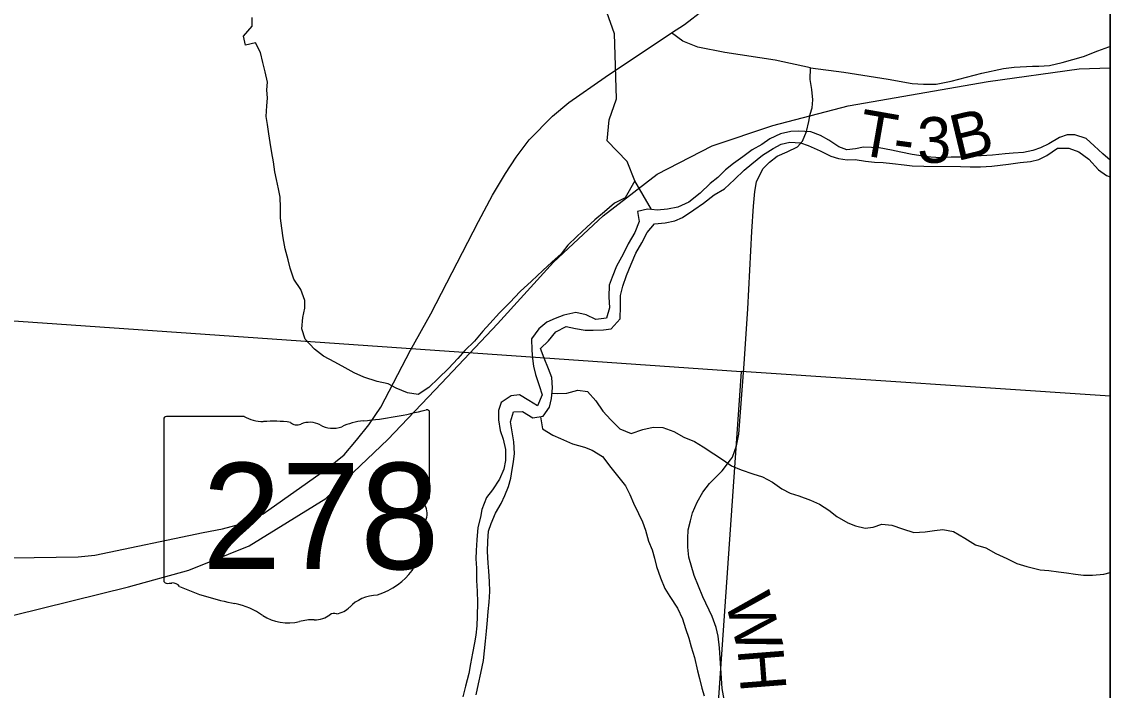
# Model space of a CAD drawing. Extents: x 0 to 34, y 0 to 22.
# Drawn here: x 7.55 to 8.9, y 19.403 to 20.232 of the extents above; entities that cross this region are included whole.
import ezdxf

# ---------------------------------------------------------------- set-up
doc = ezdxf.new("R2010")
doc.units = 0
for name, color, linetype in [('Default', 7, 'Continuous'), ('GM_X_County_Road', 7, 'Continuous'), ('GM_X_County_Road_Text', 7, 'Continuous'), ('GM_X_Major_River', 7, 'Continuous'), ('GM_X_Minor_River', 7, 'Continuous'), ('GM_X_Rail_Line', 7, 'Continuous'), ('GM_X_Section', 7, 'Continuous'), ('GM_X_State_Location', 7, 'Continuous'), ('GM_X_State_Route', 7, 'Continuous'), ('GM_X_State_Shield', 7, 'Continuous'), ('GM_X_Township_Road', 7, 'Continuous'), ('GM_X_Township_Road_Text', 7, 'Continuous'), ('SC_Scratch1', 7, 'Continuous'), ('SH_Data', 7, 'Continuous')]:
    doc.layers.add(name, color=color, linetype=linetype)

msp = doc.modelspace()

# ---------------------------------------------------------------- linework, layer by layer
at = {"layer": 'Default'}
msp.add_lwpolyline([(8.9, 18.739), (8.9, 19.7676), (8.4423, 19.798), (8.3709, 18.7757)], close=True, dxfattribs=at)
at = {"layer": 'GM_X_County_Road'}
msp.add_lwpolyline([(8.421, 19.3911), (8.4184, 19.4049), (8.4154, 19.4552), (8.4137, 19.47), (8.4111, 19.4808), (8.406, 19.4942), (8.3947, 19.5188), (8.3839, 19.5452), (8.3774, 19.5679), (8.3759, 19.5801), (8.3759, 19.5912), (8.3766, 19.6018), (8.3794, 19.613), (8.3818, 19.6227), (8.3875, 19.6359), (8.3945, 19.6485), (8.4029, 19.6591), (8.4184, 19.675), (8.4288, 19.6884), (8.4314, 19.6921), (8.4363, 19.706), (8.4391, 19.7203), (8.4459, 19.8075), (8.4504, 19.8758), (8.4556, 19.9719), (8.4574, 20.0031), (8.459, 20.0216), (8.4614, 20.0336), (8.4691, 20.0496), (8.4774, 20.0578), (8.4868, 20.0653), (8.4994, 20.0707), (8.5119, 20.0768), (8.5183, 20.0841), (8.5231, 20.0958), (8.526, 20.1081), (8.5279, 20.1175), (8.5302, 20.1254), (8.5311, 20.1351), (8.5298, 20.148), (8.5278, 20.1602), (8.5281, 20.1748), (8.4844, 20.1843), (8.422, 20.1941), (8.3884, 20.2005), (8.37, 20.2081), (8.3557, 20.2182)], dxfattribs=at)
at = {"layer": 'GM_X_Major_River'}
for points in [[(8.3104, 20.0348), (8.3009, 20.0587), (8.2758, 20.0845), (8.2784, 20.1103), (8.2874, 20.1365), (8.2866, 20.1631), (8.2858, 20.1908), (8.2849, 20.217), (8.2754, 20.244), (8.267, 20.2694), (8.2746, 20.283)], [(8.7924, 20.07), (8.7795, 20.0689), (8.7697, 20.0681), (8.7541, 20.0666), (8.7397, 20.0659), (8.7257, 20.0648), (8.7158, 20.064), (8.7025, 20.064), (8.69, 20.0633), (8.6775, 20.0641), (8.668, 20.0652), (8.6543, 20.0675), (8.6403, 20.0702), (8.6285, 20.0728), (8.6134, 20.0755), (8.6039, 20.0759), (8.594, 20.0763), (8.5838, 20.0744), (8.5731, 20.0733), (8.5633, 20.0767), (8.5508, 20.0851), (8.5405, 20.0911), (8.5284, 20.0953), (8.5136, 20.0965), (8.5037, 20.0961), (8.4908, 20.0931), (8.4779, 20.0866), (8.4677, 20.0798), (8.4559, 20.073), (8.4441, 20.0643), (8.4327, 20.0563), (8.4229, 20.0484), (8.4134, 20.0389), (8.4039, 20.0313), (8.3914, 20.0192), (8.3773, 20.0082), (8.3636, 20.0021), (8.3507, 19.9995), (8.3378, 19.9983), (8.331, 19.999)], [(8.9, 20.0604), (8.8907, 20.068), (8.8801, 20.0783), (8.8702, 20.0874), (8.8562, 20.0916), (8.8467, 20.0916), (8.8372, 20.0886), (8.8239, 20.0806), (8.8137, 20.0757), (8.8038, 20.0723), (8.7924, 20.07)], [(8.1194, 19.4238), (8.1224, 19.4398), (8.1239, 19.4515), (8.1251, 19.4637), (8.1262, 19.4762), (8.1274, 19.4895), (8.1285, 19.5005), (8.1297, 19.5119), (8.1304, 19.5252), (8.13, 19.5377), (8.1293, 19.5506), (8.1285, 19.5605), (8.1274, 19.5749), (8.1278, 19.5878), (8.1289, 19.6), (8.132, 19.6098), (8.1373, 19.6223), (8.1445, 19.6345), (8.1491, 19.6444), (8.1536, 19.6557), (8.1563, 19.666), (8.1582, 19.6766), (8.1597, 19.6861), (8.1609, 19.6963), (8.1601, 19.7108), (8.156, 19.7358), (8.1598, 19.7483), (8.1708, 19.7487), (8.1837, 19.7407), (8.1966, 19.7426), (8.2045, 19.754), (8.2068, 19.7646), (8.2083, 19.7779), (8.2072, 19.7908), (8.203, 19.8015), (8.1977, 19.8147), (8.1932, 19.8269), (8.2031, 19.8364), (8.2122, 19.8474), (8.2251, 19.8538), (8.2365, 19.8515), (8.2486, 19.8496), (8.2585, 19.8496), (8.2714, 19.85), (8.2809, 19.8511), (8.2919, 19.8636), (8.2926, 19.8792), (8.2923, 19.8925), (8.2953, 19.9042), (8.2999, 19.9171), (8.3056, 19.9315), (8.3116, 19.9448), (8.3189, 19.9577), (8.3257, 19.9706), (8.3348, 19.9813), (8.3477, 19.9824), (8.3598, 19.985), (8.3693, 19.9892), (8.3834, 19.9987), (8.3955, 20.007), (8.4088, 20.0172), (8.4213, 20.0248), (8.4339, 20.0362), (8.446, 20.048), (8.4555, 20.0559), (8.4688, 20.0665), (8.4817, 20.0749), (8.4916, 20.0802), (8.5026, 20.0828), (8.5158, 20.082), (8.5253, 20.0786), (8.5401, 20.0718), (8.5534, 20.0653), (8.5629, 20.0623), (8.5735, 20.0607), (8.5834, 20.0611), (8.5966, 20.0592), (8.6076, 20.058), (8.6183, 20.0573), (8.6297, 20.0561), (8.6445, 20.0546), (8.6543, 20.0534), (8.6687, 20.0527), (8.7143, 20.0526), (8.7264, 20.0522), (8.7389, 20.0522), (8.753, 20.053), (8.7636, 20.0541), (8.7738, 20.0552), (8.7883, 20.0575), (8.8012, 20.0586), (8.8114, 20.0613), (8.8213, 20.0662), (8.8346, 20.0753), (8.8486, 20.0753), (8.8611, 20.0707), (8.8736, 20.0616), (8.8854, 20.0483), (8.8952, 20.0415), (8.9, 20.0395)], [(8.331, 19.999), (8.3104, 20.0348)], [(8.331, 19.999), (8.3261, 19.9995), (8.3136, 19.9965), (8.3155, 19.9843), (8.3101, 19.9706), (8.3022, 19.9566), (8.2957, 19.9437), (8.2877, 19.9289), (8.282, 19.9153), (8.2786, 19.9054), (8.2782, 19.8906), (8.279, 19.8773), (8.2752, 19.8644), (8.2619, 19.8625), (8.2497, 19.8686), (8.2369, 19.8713), (8.2224, 19.8679), (8.2114, 19.8641), (8.2012, 19.8592), (8.1913, 19.8512), (8.1822, 19.8387), (8.1826, 19.8246), (8.1833, 19.8144), (8.1845, 19.8049), (8.1871, 19.7946), (8.1916, 19.7806), (8.1954, 19.7692), (8.1894, 19.7555), (8.1787, 19.7624), (8.167, 19.7692), (8.1567, 19.7681), (8.1446, 19.7598), (8.1412, 19.7499), (8.1412, 19.7381), (8.1434, 19.7248), (8.1468, 19.7142), (8.1499, 19.7013), (8.1499, 19.6876), (8.1476, 19.677), (8.1423, 19.6645), (8.1335, 19.6512), (8.1263, 19.6417), (8.1206, 19.6269), (8.1187, 19.6174), (8.1157, 19.6045), (8.1141, 19.5893), (8.1134, 19.5761), (8.113, 19.5658), (8.1137, 19.554), (8.1137, 19.5389), (8.1145, 19.5256), (8.1149, 19.5115), (8.1145, 19.4948), (8.1141, 19.4827), (8.1129, 19.4709), (8.1114, 19.4614), (8.1091, 19.4489), (8.1065, 19.4356), (8.1042, 19.4235), (8.1004, 19.4079), (8.097, 19.3946)], [(8.1133, 19.3969), (8.1163, 19.4109), (8.1194, 19.4238)]]:
    msp.add_lwpolyline(points, dxfattribs=at)
at = {"layer": 'GM_X_Minor_River'}
for points in [[(8.3104, 20.0348), (8.2982, 20.0138), (8.2849, 20.0069), (8.2728, 19.9963), (8.2607, 19.9865), (8.2509, 19.9774), (8.2384, 19.9656), (8.227, 19.955), (8.2187, 19.9443), (8.2074, 19.9337), (8.196, 19.9235), (8.182, 19.9102), (8.168, 19.8973), (8.1552, 19.8836), (8.1423, 19.8711), (8.1306, 19.8578), (8.1219, 19.8484), (8.1113, 19.8358), (8.0992, 19.8241), (8.0909, 19.8142), (8.0792, 19.8017), (8.0667, 19.7899), (8.0546, 19.7782), (8.0413, 19.7698), (8.0281, 19.7717), (8.0144, 19.7774), (8.0042, 19.7827), (7.9906, 19.7857), (7.9739, 19.791), (7.9622, 19.7967), (7.9508, 19.8028), (7.9383, 19.8096), (7.9239, 19.8172), (7.9129, 19.8259), (7.9015, 19.8384), (7.8973, 19.8509), (7.8985, 19.8653), (7.9011, 19.8767), (7.9007, 19.8862), (7.8958, 19.8998), (7.8874, 19.9127), (7.8829, 19.9264), (7.8802, 19.9366), (7.8764, 19.9502), (7.8741, 19.9639), (7.8722, 19.976), (7.8707, 19.9885), (7.8707, 20.0018), (7.8703, 20.0143), (7.8684, 20.0246), (7.8657, 20.0363), (7.8638, 20.0458), (7.8619, 20.0583), (7.86, 20.0693), (7.8577, 20.0822), (7.8562, 20.0932), (7.8547, 20.1046), (7.8531, 20.1144), (7.8539, 20.1277), (7.8546, 20.1372), (7.8539, 20.1474), (7.8546, 20.1573), (7.8519, 20.1698), (7.8489, 20.1815), (7.8459, 20.1941), (7.8398, 20.2058), (7.8273, 20.2028), (7.825, 20.2141), (7.8356, 20.2267), (7.8356, 20.2373)], [(8.2076, 19.7714), (8.214, 19.7707), (8.2261, 19.7711), (8.2394, 19.7749), (8.2515, 19.7733), (8.2617, 19.7616), (8.2704, 19.7491), (8.2807, 19.7381), (8.2917, 19.7271), (8.3057, 19.7214), (8.3201, 19.7264), (8.3329, 19.729), (8.345, 19.7286), (8.3587, 19.7237), (8.3712, 19.7169), (8.3841, 19.7112), (8.3951, 19.7048), (8.4083, 19.6961), (8.4189, 19.6892), (8.4303, 19.6813), (8.442, 19.676), (8.4568, 19.6714), (8.4686, 19.6676), (8.4811, 19.6608), (8.4928, 19.6525), (8.503, 19.6472), (8.5136, 19.6438), (8.528, 19.6385), (8.5394, 19.6336), (8.5508, 19.626), (8.561, 19.6184), (8.5743, 19.6104), (8.5841, 19.6067), (8.5962, 19.604), (8.6061, 19.6051), (8.6167, 19.6086), (8.6292, 19.6074), (8.6424, 19.6029), (8.6564, 19.5983), (8.6705, 19.5991), (8.6818, 19.601), (8.6924, 19.6022), (8.7057, 19.5995), (8.7197, 19.5915), (8.733, 19.5832), (8.7455, 19.5794), (8.758, 19.5722), (8.7716, 19.5662), (8.7841, 19.5601), (8.7966, 19.5563), (8.8129, 19.5522), (8.8239, 19.5514), (8.836, 19.5495), (8.8458, 19.5484), (8.8568, 19.5469), (8.867, 19.5457), (8.878, 19.5454), (8.892, 19.5469), (8.9, 19.5489)], [(8.1931, 19.7421), (8.1959, 19.7271), (8.2084, 19.7191), (8.2182, 19.7149), (8.233, 19.7085), (8.2478, 19.7043), (8.2572, 19.7005), (8.2701, 19.6926), (8.2804, 19.6789), (8.2986, 19.6562), (8.3042, 19.6456), (8.3088, 19.635), (8.3149, 19.6221), (8.3198, 19.6118), (8.3236, 19.6012), (8.3274, 19.5876), (8.3316, 19.577), (8.3346, 19.5667), (8.3373, 19.5561), (8.3422, 19.5421), (8.3475, 19.5288), (8.3536, 19.5189), (8.3631, 19.5045), (8.3692, 19.4913), (8.373, 19.4795), (8.3771, 19.4674), (8.3802, 19.4568), (8.3844, 19.4435), (8.3882, 19.4268), (8.3905, 19.4173), (8.3935, 19.4052), (8.3962, 19.3957)]]:
    msp.add_lwpolyline(points, dxfattribs=at)
at = {"layer": 'GM_X_Rail_Line'}
msp.add_lwpolyline([(7.54, 19.4957), (7.6823, 19.531), (7.7571, 19.5516), (7.832, 19.5819), (7.9268, 19.6406), (8.0039, 19.714), (8.0706, 19.7835), (8.14, 19.8572), (8.2095, 19.9338), (8.271, 19.9913), (8.338, 20.0428), (8.4063, 20.0783), (8.4813, 20.1033), (8.5748, 20.1279), (8.7485, 20.158), (8.8613, 20.1738), (8.9, 20.175)], dxfattribs=at)
at = {"layer": 'GM_X_Section'}
msp.add_lwpolyline([(8.4423, 19.798), (8.3709, 18.7757), (7.3808, 18.8429), (7.462, 19.8663)], close=True, dxfattribs=at)
at = {"layer": 'GM_X_State_Route'}
msp.add_lwpolyline([(7.5044, 19.567), (7.5653, 19.5673), (7.6197, 19.5683), (7.6405, 19.5704), (7.7748, 19.5985), (7.7987, 19.6031), (7.8219, 19.6092), (7.8494, 19.6218), (7.9283, 19.6775), (7.9495, 19.6946), (7.9651, 19.7129), (7.9803, 19.7322), (7.995, 19.7539), (8.0318, 19.8247), (8.0571, 19.8695), (8.1165, 19.9841), (8.1339, 20.017), (8.1499, 20.0438), (8.163, 20.0641), (8.1792, 20.0855), (8.2082, 20.1149), (8.2284, 20.132), (8.2734, 20.1632), (8.3557, 20.2182), (8.3718, 20.2287), (8.3953, 20.247)], dxfattribs=at)
at = {"layer": 'GM_X_State_Shield'}
for p, q in [((7.8257, 19.7425), (7.7292, 19.7425)), ((8.0555, 19.6427), (8.0555, 19.7474)), ((7.726, 19.739), (7.726, 19.5389)), ((8.0555, 19.6428), (8.0555, 19.6427))]:
    msp.add_line(p, q, dxfattribs=at)
for centre, major_axis, start_param, end_param in [((7.7297, 19.7395), (0.00382, 0), 1.712693, 3.28349), ((7.8487, 19.7657), (0.037, 0), 4.042523, 4.731795), ((7.9381, 20.0153), (0.3495, 0), 4.814394, 5.042369), ((8.0519, 19.7479), (0.00367, 0), 6.141152, 7.989035), ((7.861, 19.6301), (0.133, 0), 1.404758, 1.657858), ((7.8912, 19.7405), (0.0107, 0), 3.836095, 5.185415), ((7.9069, 19.7174), (0.0222, 0), 0.950623, 2.079405), ((7.9355, 19.7491), (0.0267, 0), 4.081561, 5.145723), ((7.9827, 19.6813), (0.0703, 0), 1.699011, 2.107814), ((8.0547, 19.6351), (0.00568, 0), 1.883978, 3.671073), ((8.0186, 19.6218), (0.0341, 0), 5.934695, 6.695948), ((8.0516, 19.6423), (0.00393, 0), 5.05454, 6.418171), ((8.0687, 19.5989), (0.0248, 0), 2.387724, 3.262537), ((7.9577, 19.5856), (0.0874, 0), 5.101752, 6.440018), ((7.7298, 19.5385), (0.00385, 0), 3.00124, 4.508301), ((7.7304, 19.5589), (0.0294, 0), 4.665946, 4.897461), ((7.7364, 19.5274), (0.0106, 0), 0.519207, 1.627899), ((7.8702, 19.7072), (0.2524, 0), 4.195997, 4.488961), ((7.9946, 19.4827), (0.0479, 0), 1.647645, 2.488434), ((7.7949, 19.449), (0.079, 0), 0.823519, 1.323587), ((7.9371, 19.492), (0.00752, 0), 1.147584, 2.315152), ((7.9339, 19.5195), (0.0282, 0), 4.937069, 5.64225), ((7.8804, 19.5264), (0.0501, 0), 4.026481, 4.996735), ((7.9093, 19.4572), (0.0412, 0), 1.495662, 1.94098), ((7.913, 19.5114), (0.0267, 0), 4.691044, 5.507374)]:
    msp.add_ellipse(centre, major_axis=major_axis, ratio=0.8, start_param=start_param, end_param=end_param, dxfattribs=at)
at = {"layer": 'GM_X_Township_Road'}
msp.add_lwpolyline([(8.5281, 20.1748), (8.5697, 20.1693), (8.6244, 20.1609), (8.6544, 20.1555), (8.6685, 20.1546), (8.684, 20.1546), (8.7026, 20.1585), (8.7408, 20.1681), (8.7676, 20.174), (8.7808, 20.1755), (8.8036, 20.1769), (8.8113, 20.1771), (8.8245, 20.1776), (8.8402, 20.1815), (8.8669, 20.189), (8.8846, 20.1961), (8.8984, 20.2008), (8.9, 20.2012)], dxfattribs=at)
at = {"layer": 'SC_Scratch1'}
msp.add_lwpolyline([(8.9, 18.7389), (8.9, 20.9), (5.53, 20.9), (5.4955, 20.3864), (5.4469, 19.6641), (5.4089, 19.0989), (5.4007, 18.9779), (5.4885, 18.9719), (5.9889, 18.9377), (6.8273, 18.8804), (7.2159, 18.8539), (8.2061, 18.7863)], close=True, dxfattribs=at)
at = {"layer": 'SH_Data'}
msp.add_line((8.9, 20.9), (8.9, 14.1), dxfattribs=at)

# ---------------------------------------------------------------- texts
at = {"layer": 'GM_X_County_Road_Text'}
for s, rotation, p in [('W', 284.2912, (8.4218, 19.5148)), ('H', 274.4778, (8.4377, 19.4535))]:
    msp.add_text(s, height=0.0568, rotation=rotation, dxfattribs=at).set_placement(p)
at = {"layer": 'GM_X_State_Location'}
for s in ['s', 'r']:
    msp.add_text(s, height=0.000189, dxfattribs=at).set_placement((7.887, 19.6257))
msp.add_text('278', height=0.000189, rotation=0, dxfattribs=at).set_placement((7.8202, 19.6119))
at = {"layer": 'GM_X_State_Shield'}
msp.add_text('278', height=0.13184, dxfattribs=at).set_placement((7.7736, 19.553))
at = {"layer": 'GM_X_Township_Road_Text'}
for s, rotation, p in [('T', 350.0938, (8.5843, 20.068)), ('B', 13.4814, (8.7094, 20.0589)), ('3', 0.8205, (8.6608, 20.0567)), ('-', 352.2641, (8.6285, 20.0604))]:
    msp.add_text(s, height=0.0568, rotation=rotation, dxfattribs=at).set_placement(p)

doc.saveas('drawing.dxf')
